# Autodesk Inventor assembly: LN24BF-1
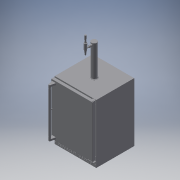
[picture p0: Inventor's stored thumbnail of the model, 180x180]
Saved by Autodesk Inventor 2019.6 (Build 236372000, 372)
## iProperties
Company: none
Created: 2025-04
Part Number: LN24BF-1
Description: CATIA V5 STEP
Document SubType Name: Assembly
Designer: MMAK
Authority: none
Title: C:\Users\MMAK\Documents\SmarTeam\WEBSITE CAD\Lynx STP\LN24BF-1.stp
Author: none
Sending System: CATIA V5 STEP AP203 v2
Preprocessor: CATIA Unofficial Packaging Version SP2
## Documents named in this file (5)
- C:\Users\MMAK\Documents\SmarTeam\WEBSITE CAD\Lynx STP\LN24BF-1.iam
- C:\Users\MMAK\Documents\SmarTeam\WEBSITE CAD\Lynx STP\VORE224-SS41A.iam
- C:\Users\MMAK\Documents\SmarTeam\WEBSITE CAD\Lynx STP\OC UC 24.ipt
- C:\Users\MMAK\Documents\SmarTeam\WEBSITE CAD\Lynx STP\Product90.iam
- C:\Users\MMAK\Documents\SmarTeam\WEBSITE CAD\Lynx STP\Beer Tap.ipt
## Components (4 placed, 4 different names)
1. VORE224-SS41A.1 [sub-assembly]
2. OC UC 24.1
3. Product90.2 [sub-assembly]
4. Beer Tap.1
